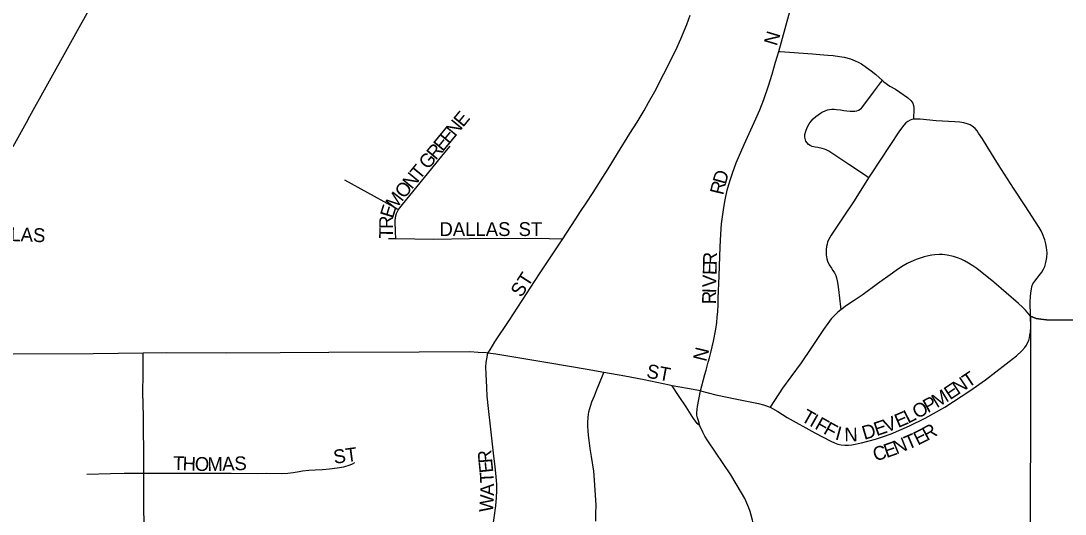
# Model space of a CAD drawing. Extents: x 1772825 to 1773716, y 1138558 to 1139032.
# Drawn here: x 1773356.3 to 1773370.59, y 1138894.47 to 1138901.21 of the extents above; entities that cross this region are included whole.
import ezdxf

# ---------------------------------------------------------------- set-up
doc = ezdxf.new("R2010")
doc.units = 0
for name, color, linetype in [('GM_X_City_Street', 7, 'Continuous'), ('GM_X_City_Street_Text', 7, 'Continuous'), ('GM_X_Corporation', 7, 'Continuous'), ('GM_X_State_Route', 7, 'Continuous'), ('GM_X_Township_Road', 7, 'Continuous')]:
    doc.layers.add(name, color=color, linetype=linetype)

msp = doc.modelspace()

# ---------------------------------------------------------------- linework, layer by layer
at = {"layer": 'GM_X_City_Street'}
for points in [[(1773366.67, 1138900.793), (1773366.811, 1138901.29), (1773366.868, 1138901.492), (1773367.048, 1138902.125), (1773367.17, 1138902.566), (1773367.263, 1138902.904), (1773367.462, 1138903.661), (1773367.635, 1138904.335), (1773367.733, 1138904.722), (1773367.815, 1138904.997), (1773367.864, 1138905.138), (1773367.93, 1138905.3), (1773367.959, 1138905.366)], [(1773363.715, 1138898.229), (1773363.827, 1138898.398), (1773363.893, 1138898.503), (1773363.961, 1138898.606), (1773364.036, 1138898.72), (1773364.132, 1138898.866), (1773364.266, 1138899.075), (1773364.338, 1138899.19), (1773364.465, 1138899.398), (1773364.634, 1138899.671), (1773364.733, 1138899.828), (1773364.829, 1138899.987), (1773364.891, 1138900.095), (1773364.974, 1138900.247), (1773365.1, 1138900.489), (1773365.261, 1138900.81), (1773365.333, 1138900.967), (1773365.413, 1138901.161), (1773365.458, 1138901.289)], [(1773365.599, 1138896.152), (1773365.661, 1138896.377), (1773365.678, 1138896.436), (1773365.707, 1138896.543), (1773365.722, 1138896.604), (1773365.742, 1138896.674), (1773365.779, 1138896.83), (1773365.81, 1138896.996), (1773365.824, 1138897.085), (1773365.827, 1138897.157), (1773365.837, 1138897.236), (1773365.84, 1138897.328), (1773365.843, 1138897.415), (1773365.856, 1138897.725), (1773365.87, 1138898.123), (1773365.879, 1138898.296), (1773365.889, 1138898.437), (1773365.905, 1138898.565), (1773365.919, 1138898.658), (1773365.938, 1138898.763), (1773365.965, 1138898.898), (1773366.001, 1138899.019), (1773366.037, 1138899.131), (1773366.089, 1138899.269), (1773366.198, 1138899.523), (1773366.358, 1138899.874), (1773366.412, 1138899.996), (1773366.467, 1138900.137), (1773366.532, 1138900.324), (1773366.579, 1138900.483), (1773366.628, 1138900.645), (1773366.67, 1138900.793)], [(1773366.67, 1138900.793), (1773366.689, 1138900.792), (1773367.132, 1138900.76), (1773367.231, 1138900.754), (1773367.343, 1138900.744), (1773367.417, 1138900.737), (1773367.504, 1138900.725), (1773367.566, 1138900.714), (1773367.651, 1138900.691), (1773367.716, 1138900.667), (1773367.759, 1138900.646), (1773367.801, 1138900.624), (1773367.872, 1138900.573), (1773367.933, 1138900.529), (1773367.997, 1138900.479), (1773368.089, 1138900.395)], [(1773367.901, 1138899.066), (1773367.87, 1138899.086), (1773367.628, 1138899.249), (1773367.398, 1138899.404), (1773367.354, 1138899.431), (1773367.319, 1138899.447), (1773367.296, 1138899.456), (1773367.263, 1138899.466), (1773367.207, 1138899.478), (1773367.17, 1138899.484), (1773367.129, 1138899.495), (1773367.1, 1138899.507), (1773367.077, 1138899.523), (1773367.058, 1138899.542), (1773367.043, 1138899.565), (1773367.035, 1138899.586), (1773367.028, 1138899.622), (1773367.029, 1138899.658), (1773367.04, 1138899.703), (1773367.061, 1138899.755), (1773367.088, 1138899.804), (1773367.115, 1138899.84), (1773367.141, 1138899.87), (1773367.18, 1138899.904), (1773367.21, 1138899.929), (1773367.242, 1138899.95), (1773367.269, 1138899.966), (1773367.297, 1138899.979), (1773367.338, 1138899.994), (1773367.366, 1138900), (1773367.397, 1138900.003), (1773367.428, 1138900.003), (1773367.462, 1138900), (1773367.515, 1138899.993), (1773367.56, 1138899.987), (1773367.601, 1138899.982), (1773367.648, 1138899.977), (1773367.674, 1138899.977), (1773367.71, 1138899.979), (1773367.741, 1138899.983), (1773367.761, 1138899.989), (1773367.785, 1138900.003), (1773367.802, 1138900.018), (1773367.82, 1138900.04), (1773367.967, 1138900.237), (1773368.064, 1138900.363), (1773368.089, 1138900.395)], [(1773368.089, 1138900.395), (1773368.11, 1138900.377), (1773368.191, 1138900.321), (1773368.266, 1138900.276), (1773368.327, 1138900.237), (1773368.432, 1138900.165), (1773368.48, 1138900.121), (1773368.503, 1138900.088), (1773368.513, 1138900.056), (1773368.517, 1138900.021), (1773368.517, 1138899.983), (1773368.516, 1138899.899), (1773368.515, 1138899.866)], [(1773368.515, 1138899.866), (1773368.49, 1138899.862), (1773368.467, 1138899.852), (1773368.435, 1138899.835), (1773368.411, 1138899.817), (1773368.38, 1138899.786), (1773368.324, 1138899.707), (1773367.927, 1138899.108), (1773367.901, 1138899.066)], [(1773370.114, 1138897.173), (1773370.111, 1138897.369), (1773370.116, 1138897.444), (1773370.119, 1138897.492), (1773370.127, 1138897.543), (1773370.133, 1138897.577), (1773370.148, 1138897.613), (1773370.174, 1138897.653), (1773370.204, 1138897.691), (1773370.235, 1138897.73), (1773370.268, 1138897.773), (1773370.295, 1138897.816), (1773370.313, 1138897.854), (1773370.327, 1138897.908), (1773370.337, 1138897.975), (1773370.342, 1138898.038), (1773370.336, 1138898.11), (1773370.326, 1138898.162), (1773370.312, 1138898.219), (1773370.279, 1138898.301), (1773370.26, 1138898.341), (1773370.234, 1138898.385), (1773370.043, 1138898.681), (1773369.884, 1138898.926), (1773369.678, 1138899.245), (1773369.52, 1138899.493), (1773369.457, 1138899.598), (1773369.403, 1138899.678), (1773369.384, 1138899.709), (1773369.356, 1138899.742), (1773369.318, 1138899.773), (1773369.288, 1138899.791), (1773369.25, 1138899.804), (1773369.205, 1138899.817), (1773369.149, 1138899.826), (1773369.08, 1138899.829), (1773368.825, 1138899.847), (1773368.606, 1138899.866), (1773368.55, 1138899.869), (1773368.515, 1138899.866)], [(1773361.471, 1138898.63), (1773361.471, 1138898.631), (1773361.522, 1138898.701), (1773361.925, 1138899.191), (1773362.081, 1138899.384), (1773362.177, 1138899.498)], [(1773360.731, 1138899.037), (1773361.359, 1138898.692), (1773361.471, 1138898.63)], [(1773367.901, 1138899.066), (1773367.702, 1138898.751), (1773367.554, 1138898.529), (1773367.452, 1138898.375), (1773367.39, 1138898.281), (1773367.353, 1138898.218), (1773367.339, 1138898.184), (1773367.332, 1138898.156), (1773367.324, 1138898.124), (1773367.32, 1138898.086), (1773367.321, 1138898.014), (1773367.329, 1138897.956), (1773367.337, 1138897.927), (1773367.362, 1138897.876), (1773367.391, 1138897.828), (1773367.411, 1138897.799), (1773367.432, 1138897.766), (1773367.451, 1138897.731), (1773367.46, 1138897.697), (1773367.472, 1138897.654), (1773367.48, 1138897.606), (1773367.49, 1138897.536), (1773367.517, 1138897.3), (1773367.521, 1138897.259)], [(1773361.434, 1138898.233), (1773361.43, 1138898.325), (1773361.425, 1138898.467), (1773361.43, 1138898.529), (1773361.443, 1138898.576), (1773361.471, 1138898.63)], [(1773361.332, 1138898.233), (1773361.434, 1138898.233)], [(1773361.434, 1138898.233), (1773361.953, 1138898.228), (1773362.438, 1138898.233), (1773363.345, 1138898.239), (1773363.715, 1138898.229)], [(1773362.693, 1138896.667), (1773362.721, 1138896.713), (1773362.788, 1138896.822), (1773362.981, 1138897.113), (1773363.399, 1138897.75), (1773363.715, 1138898.229)], [(1773370.114, 1138897.173), (1773370.047, 1138897.254), (1773370.007, 1138897.298), (1773369.951, 1138897.346), (1773369.612, 1138897.637), (1773369.379, 1138897.823), (1773369.327, 1138897.86), (1773369.266, 1138897.9), (1773369.21, 1138897.929), (1773369.166, 1138897.951), (1773369.115, 1138897.972), (1773369.061, 1138897.99), (1773368.976, 1138898.008), (1773368.913, 1138898.015), (1773368.865, 1138898.015), (1773368.804, 1138898.011), (1773368.765, 1138898.005), (1773368.719, 1138897.996), (1773368.659, 1138897.984), (1773368.605, 1138897.965), (1773368.553, 1138897.947), (1773368.479, 1138897.917), (1773368.426, 1138897.892), (1773368.372, 1138897.861), (1773368.297, 1138897.812), (1773368.225, 1138897.763), (1773368.02, 1138897.614), (1773367.826, 1138897.471), (1773367.701, 1138897.388), (1773367.599, 1138897.317), (1773367.521, 1138897.259)], [(1773367.521, 1138897.259), (1773367.48, 1138897.228), (1773367.428, 1138897.177), (1773367.388, 1138897.136), (1773367.341, 1138897.073), (1773367.283, 1138896.989), (1773367.191, 1138896.854), (1773367.11, 1138896.729), (1773366.976, 1138896.535), (1773366.836, 1138896.341), (1773366.723, 1138896.186), (1773366.554, 1138895.93)], [(1773366.554, 1138895.93), (1773366.659, 1138895.87), (1773366.788, 1138895.787), (1773367.165, 1138895.575), (1773367.385, 1138895.464), (1773367.433, 1138895.441), (1773367.48, 1138895.422), (1773367.524, 1138895.412), (1773367.574, 1138895.406), (1773367.623, 1138895.406), (1773367.669, 1138895.413), (1773367.804, 1138895.439), (1773367.996, 1138895.492), (1773368.089, 1138895.523), (1773368.208, 1138895.565), (1773368.344, 1138895.622), (1773368.46, 1138895.672), (1773368.672, 1138895.776), (1773368.941, 1138895.93), (1773369.286, 1138896.153), (1773369.5, 1138896.303), (1773369.924, 1138896.631), (1773369.998, 1138896.697), (1773370.038, 1138896.744), (1773370.058, 1138896.775), (1773370.076, 1138896.808), (1773370.091, 1138896.841), (1773370.101, 1138896.878), (1773370.107, 1138896.913), (1773370.113, 1138896.952), (1773370.118, 1138897.023), (1773370.114, 1138897.173)], [(1773357.974, 1138896.668), (1773357.294, 1138896.659), (1773356.2, 1138896.655), (1773355.07, 1138896.65), (1773354.603, 1138896.658)], [(1773357.983, 1138895.027), (1773357.983, 1138895.108), (1773357.983, 1138895.364), (1773357.982, 1138895.588), (1773357.981, 1138895.799), (1773357.972, 1138896.135), (1773357.974, 1138896.371), (1773357.974, 1138896.584), (1773357.974, 1138896.668)], [(1773362.693, 1138896.667), (1773362.667, 1138896.67), (1773362.561, 1138896.678), (1773362.445, 1138896.683), (1773361.751, 1138896.682), (1773360.518, 1138896.675), (1773359.85, 1138896.671), (1773359.119, 1138896.668), (1773358.299, 1138896.673), (1773357.974, 1138896.668)], [(1773362.562, 1138893.462), (1773362.631, 1138893.666), (1773362.679, 1138893.844), (1773362.702, 1138893.958), (1773362.743, 1138894.167), (1773362.778, 1138894.416), (1773362.801, 1138894.579), (1773362.809, 1138894.694), (1773362.816, 1138894.79), (1773362.814, 1138894.877), (1773362.806, 1138894.976), (1773362.793, 1138895.115), (1773362.774, 1138895.258), (1773362.733, 1138895.628), (1773362.699, 1138895.912), (1773362.684, 1138896.08), (1773362.677, 1138896.195), (1773362.666, 1138896.382), (1773362.664, 1138896.476), (1773362.669, 1138896.54), (1773362.676, 1138896.587), (1773362.693, 1138896.667)], [(1773364.278, 1138896.403), (1773364.051, 1138896.443), (1773363.537, 1138896.528), (1773362.802, 1138896.654), (1773362.693, 1138896.667)], [(1773364.167, 1138894.367), (1773364.168, 1138894.467), (1773364.171, 1138894.587), (1773364.165, 1138894.724), (1773364.15, 1138894.93), (1773364.141, 1138895.053), (1773364.107, 1138895.253), (1773364.092, 1138895.364), (1773364.077, 1138895.473), (1773364.067, 1138895.542), (1773364.062, 1138895.611), (1773364.059, 1138895.662), (1773364.06, 1138895.72), (1773364.062, 1138895.791), (1773364.074, 1138895.865), (1773364.087, 1138895.912), (1773364.114, 1138896.001), (1773364.148, 1138896.085), (1773364.178, 1138896.156), (1773364.269, 1138896.381), (1773364.278, 1138896.403)], [(1773365.211, 1138896.221), (1773365.178, 1138896.227), (1773364.831, 1138896.301), (1773364.564, 1138896.352), (1773364.278, 1138896.403)], [(1773365.599, 1138896.152), (1773365.423, 1138896.183), (1773365.211, 1138896.221)], [(1773365.592, 1138895.674), (1773365.557, 1138895.704), (1773365.53, 1138895.736), (1773365.497, 1138895.786), (1773365.404, 1138895.932), (1773365.3, 1138896.086), (1773365.211, 1138896.221)], [(1773365.592, 1138895.674), (1773365.571, 1138895.74), (1773365.56, 1138895.781), (1773365.552, 1138895.818), (1773365.551, 1138895.85), (1773365.554, 1138895.899), (1773365.559, 1138895.937), (1773365.599, 1138896.152)], [(1773365.599, 1138896.152), (1773365.809, 1138896.097), (1773366.096, 1138896.037), (1773366.396, 1138895.977), (1773366.462, 1138895.961), (1773366.554, 1138895.93)], [(1773366.318, 1138891.804), (1773366.328, 1138892.208), (1773366.344, 1138892.813), (1773366.356, 1138893.608), (1773366.352, 1138894.08), (1773366.344, 1138894.165), (1773366.34, 1138894.239), (1773366.325, 1138894.327), (1773366.314, 1138894.384), (1773366.295, 1138894.449), (1773366.281, 1138894.502), (1773366.263, 1138894.551), (1773366.236, 1138894.616), (1773366.208, 1138894.68), (1773366.163, 1138894.758), (1773366.014, 1138895.001), (1773365.702, 1138895.467), (1773365.659, 1138895.533), (1773365.631, 1138895.585), (1773365.592, 1138895.674)], [(1773357.983, 1138895.027), (1773358.434, 1138895.026), (1773358.633, 1138895.025), (1773358.906, 1138895.024), (1773359.179, 1138895.024), (1773359.539, 1138895.022), (1773359.664, 1138895.023), (1773359.875, 1138895.022), (1773359.956, 1138895.027), (1773360.026, 1138895.036), (1773360.108, 1138895.05), (1773360.157, 1138895.058), (1773360.243, 1138895.064), (1773360.33, 1138895.07), (1773360.427, 1138895.077), (1773360.526, 1138895.086), (1773360.629, 1138895.097), (1773360.723, 1138895.114), (1773360.806, 1138895.14), (1773360.84, 1138895.155), (1773360.872, 1138895.171)], [(1773357.206, 1138895.013), (1773357.528, 1138895.022), (1773357.714, 1138895.026), (1773357.983, 1138895.027)], [(1773357.989, 1138893.467), (1773357.989, 1138893.481), (1773357.988, 1138894.27), (1773357.985, 1138894.618), (1773357.983, 1138894.879), (1773357.983, 1138895.027)]]:
    msp.add_lwpolyline(points, dxfattribs=at)
at = {"layer": 'GM_X_Corporation'}
msp.add_lwpolyline([(1773375, 1138897.091), (1773370.336, 1138897.124), (1773370.258, 1138897.13), (1773370.194, 1138897.143), (1773370.114, 1138897.173), (1773370.116, 1138897.078), (1773370.104, 1138889.429)], dxfattribs=at)
at = {"layer": 'GM_X_State_Route'}
for points in [[(1773356.404, 1138899.868), (1773356.672, 1138900.351), (1773357.276, 1138901.442), (1773357.655, 1138902.127), (1773357.979, 1138902.711), (1773358.161, 1138903.038), (1773358.62, 1138903.862), (1773358.798, 1138904.183)], [(1773356.196, 1138899.492), (1773356.401, 1138899.862), (1773356.404, 1138899.868)]]:
    msp.add_lwpolyline(points, dxfattribs=at)
at = {"layer": 'GM_X_Township_Road'}
msp.add_lwpolyline([(1773370.114, 1138897.173), (1773370.194, 1138897.143), (1773370.258, 1138897.13), (1773370.336, 1138897.124), (1773370.467, 1138897.121), (1773370.776, 1138897.121), (1773371.26, 1138897.119), (1773371.813, 1138897.117), (1773372.305, 1138897.114), (1773372.708, 1138897.11), (1773373.264, 1138897.104), (1773373.935, 1138897.097), (1773374.803, 1138897.091), (1773375, 1138897.091), (1773375.117, 1138897.092)], dxfattribs=at)

# ---------------------------------------------------------------- texts
at = {"layer": 'GM_X_City_Street_Text'}
for s, height, rotation, p in [('N', 0.189, 73.3128, (1773366.645, 1138900.86)), ('E', 0.189, 50.5722, (1773362.351, 1138899.748)), ('N', 0.189, 50.5582, (1773362.245, 1138899.62)), ('E', 0.189, 50.5722, (1773362.16, 1138899.517)), ('E', 0.189, 50.557, (1773362.075, 1138899.414)), ('G', 0.189, 50.574, (1773361.874, 1138899.169)), ('R', 0.189, 50.5739, (1773361.98, 1138899.298)), ('T', 0.189, 50.5722, (1773361.758, 1138899.027)), ('N', 0.189, 50.574, (1773361.652, 1138898.899)), ('D', 0.189, 74.3519, (1773365.945, 1138898.965)), ('O', 0.189, 50.5722, (1773361.546, 1138898.77)), ('R', 0.189, 76.4703, (1773365.91, 1138898.821)), ('M', 0.189, 52.1538, (1773361.424, 1138898.613)), ('E', 0.189, 72.9214, (1773361.393, 1138898.502)), ('DALLAS', 0.1894, 357.8801, (1773355.664, 1138898.219)), ('R', 0.189, 89.5871, (1773361.394, 1138898.366)), ('DALLAS', 0.1894, 0, (1773362.029, 1138898.269)), ('ST', 0.1894, 0, (1773363.112, 1138898.269)), ('T', 0.189, 89.5902, (1773361.393, 1138898.233)), ('R', 0.189, 88.5868, (1773365.823, 1138897.867)), ('E', 0.189, 88.5795, (1773365.82, 1138897.734)), ('ST', 0.1894, 57.2679, (1773363.149, 1138897.419)), ('V', 0.189, 88.5917, (1773365.816, 1138897.567)), ('R', 0.189, 88.5916, (1773365.81, 1138897.334)), ('I', 0.189, 88.557, (1773365.814, 1138897.484)), ('N', 0.189, 75.9766, (1773365.678, 1138896.542)), ('ST', 0.1894, 349.3878, (1773364.852, 1138896.335)), ('T', 0.189, 33.7319, (1773369.263, 1138896.187)), ('E', 0.189, 33.6419, (1773369.013, 1138896.021)), ('N', 0.189, 33.7146, (1773369.124, 1138896.095)), ('M', 0.189, 31.0783, (1773368.834, 1138895.912)), ('O', 0.189, 28.8793, (1773368.564, 1138895.763)), ('P', 0.189, 28.9614, (1773368.71, 1138895.844)), ('T', 0.189, 330.3059, (1773366.964, 1138895.747)), ('I', 0.189, 330.266, (1773367.08, 1138895.681)), ('E', 0.189, 23.228, (1773368.305, 1138895.641)), ('L', 0.189, 27.3245, (1773368.441, 1138895.7)), ('F', 0.189, 330.3006, (1773367.152, 1138895.64)), ('F', 0.189, 330.8942, (1773367.27, 1138895.573)), ('D', 0.189, 16.2625, (1773367.841, 1138895.48)), ('E', 0.189, 19.0529, (1773368.01, 1138895.53)), ('V', 0.189, 21.8306, (1773368.146, 1138895.577)), ('R', 0.189, 28.663, (1773368.698, 1138895.464)), ('I', 0.189, 344.6891, (1773367.432, 1138895.489)), ('N', 0.189, 0.522, (1773367.569, 1138895.459)), ('T', 0.189, 23.046, (1773368.438, 1138895.343)), ('E', 0.189, 26.69, (1773368.573, 1138895.401)), ('C', 0.189, 15.9687, (1773367.989, 1138895.186)), ('E', 0.189, 19.2593, (1773368.145, 1138895.231)), ('N', 0.189, 22.1438, (1773368.28, 1138895.279)), ('ST', 0.1894, 7.5908, (1773360.591, 1138895.152)), ('R', 0.189, 95.2538, (1773362.754, 1138895.17)), ('T', 0.189, 358.2511, (1773358.38, 1138895.069)), ('H', 0.189, 358.2363, (1773358.513, 1138895.064)), ('O', 0.189, 358.2589, (1773358.68, 1138895.059)), ('M', 0.189, 0.7972, (1773358.856, 1138895.054)), ('A', 0.189, 2.0332, (1773359.06, 1138895.057)), ('S', 0.189, 2.0522, (1773359.227, 1138895.063)), ('E', 0.189, 96.1962, (1773362.768, 1138895.038)), ('T', 0.189, 92.8287, (1773362.776, 1138894.893)), ('A', 0.189, 89.6887, (1773362.775, 1138894.715)), ('W', 0.189, 86.2139, (1773362.76, 1138894.486))]:
    msp.add_text(s, height=height, rotation=rotation, dxfattribs=at).set_placement(p)

doc.saveas('drawing.dxf')
